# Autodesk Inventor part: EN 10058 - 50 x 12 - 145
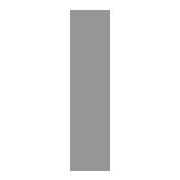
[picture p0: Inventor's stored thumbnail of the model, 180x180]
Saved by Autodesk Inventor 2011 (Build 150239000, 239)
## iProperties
IsCustomPart: 1
Created: 2010-02
Part Number: EN 10058 - 50 x 12 - 145
Material: Steel, Mild
Description: flat steel bar 50*12
Document SubType Name: Modeling
Standard: DIN
Designer: PC
Standard Revision: 2004
Standards Organization: DIN
Language: en-US
Size Designation: 50 x 12
Categories: <MemberInstance><Categories><Category DisplayName="Structural Shapes" InternalName="089c4875-fa83-4c05-b084-43b9cc11f5ed" Mnemonic="GRDR"><CategoryParameter Dis
Stock Number: 50 x 12
Density: 7.86 g/cm^3
_CCFamilyMember: 60
_CCFamilyDisplayName: DIN EN 10058 - Hot rolled flat steel bars for general purposes
_FrameMemberDoc: Frame Member File
_Version: 15.0.0
_GetPNFromCC: 1
G_L: 145.000 mm
G_W: 12.000 mm
G_H: 50.000 mm
Author: PC
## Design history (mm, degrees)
node "Start plane"
node "End plane"
sketch "Sketch"
  geometry: L1 (6, -25)-(-6, -25); L2 (-6, -25)-(-6, 25); L3 (-6, 25)-(6, 25); L4 (6, 25)-(6, -25); L5 (-6, 0)-(8, 0); L6 (0, -30)-(0, 40); L7 (0, 54)-(0, -44) reference; L8 (-9.2, 0)-(13.2, 0) reference
  constraints: 12 end point, 2 collinear, 2 parallel, 1 horizontal, 1 perpendicular
  dimensions: "d0" = 50 distance between parallel lines of L3 L1 (= G_W); "d1" = 12 distance between parallel lines of L4 L2 (= G_H); "d4" = 6 distance between parallel lines of L6 L4 (= 0.5 x d1); "d5" = 25 distance between parallel lines of L5 L3 (= 0.5 x d0)
extrude "Body" new body sketch "Sketch" stored distance "d2" = 145 (= G_L); taper "d3" = 0 deg
node "Driven Length"
  sketch "Sketch3"
    geometry: L1 (0, 0)-(10, 0) reference
    constraints: 2 end point, 1 horizontal
  workplane "Work Plane3"
  sketch "Sketch4"
    geometry: L1 (-2, 0)-(12, 0) reference; L2 (-2, 145)-(12, 145) reference
    dimensions: "d9" = 145 distance between parallel lines of L1 L2 (derived)
body "Solid1"
other parameters: "G_W" = 50 [user parameter; used in 1 equation term], "G_H" = 12 [user parameter; used in 1 equation term], "G_L" = 145 (= d9) [user parameter; used in 1 equation term], "G_OFFSET_START" = 0 [user parameter; used in 1 equation term], "G_OFFSET_END" = 0 [user parameter; used in 1 equation term], "d6" = 0 (computed from G_OFFSET_START), "d7" = 145 (= G_OFFSET_END + B_L), "B_L" = 145 [user parameter; used in 1 equation term], "d8" = 90 deg, "MAS" = 0.471 [user parameter]
